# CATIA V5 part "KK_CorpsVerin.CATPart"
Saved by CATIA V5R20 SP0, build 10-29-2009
Part number: Corps de verin accouplement
Bounding box of the stored display mesh (mm): x -175.976 to 175.976, y -111.998 to 798.499, z -2473.558 to -1168.002
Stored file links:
  G:\Khaled_CFAO_2011\ST2M\ST2M_GR2\aboulegue\Khaled\CAD_thinkMOTION\KK_CorpsVerin.CATPart
  G:\Khaled_CFAO_2011\ST2M\ST2M_GR2\aboulegue\Khaled\CAD_thinkMOTION\KK_Train_Atterrissage.CATProduct
  G:\Khaled_CFAO_2011\ST2M\ST2M_GR2\aboulegue\Khaled\CAD_thinkMOTION\KK_SqueletteVerin.CATPart
  G:\Khaled_CFAO_2011\ST2M\ST2M_GR2\aboulegue\Khaled\CAD_thinkMOTION\KK_SquelettePanneau_Pivotant.CATPart
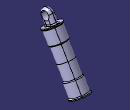
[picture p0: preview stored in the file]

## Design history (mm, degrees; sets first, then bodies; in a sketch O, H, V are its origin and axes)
External parameters (linked from other documents)
  `External.Longueur corps de verin` = 1280 mm
Set1
  Plane1 "Plan reference": linked copy from another document
  Line1: linked copy from another document
  Point1: linked copy from another document
  Line2: linked copy from another document
  Line3: linked copy from another document
  Point2 "Point.13": linked copy from another document
Body1 (main body)
  Sketch1 on Plane1, origin (0, 0, 0), H (0, 1, 0), V (0, 0, 1)
    point P1 (80.8287, -1418.0823)
    line L1 (80.8287, -1418.0823) -> (363.729, -1901.3704)
    line L2 (363.729, -1901.3704) -> (488.0031, -1828.6246)
    line L3 (488.0031, -1828.6246) -> (342.5115, -1580.0764)
    line L4 (342.5115, -1580.0764) -> (356.3197, -1571.9936)
    line L5 (356.3197, -1571.9936) -> (226.9939, -1351.0619)
    line L6 (226.9939, -1351.0619) -> (240.8021, -1342.979)
    line L7 (240.8021, -1342.979) -> (232.7192, -1329.1708)
    line L8 (232.7192, -1329.1708) -> (80.8287, -1418.0823)
    reference projected line E1 (0, -1280) -> (711.2923, -2495.1244) from Line1
    reference projected point E2 (0, -1280) from Point1
    length L1 = 560 {= (`External.Longueur corps de verin` -160mm)/2}
    length L2 = 144
    length L8 = 176
    length L6 = 16
    length L5 = 256
    length L3 = 288
    distance P1 E2 = 160
    perpendicularity: L2 L1
    parallelism: L3 L1, L4 L2, L5 L3, L6 L4, L7 L5, L8 L2
    coincidence: L1 E1
  Shaft1: profile Sketch1, axis Line1, angle 360
  Mirror1: of Shaft1, about face of Shaft1 from Sketch1.L2
  Sketch2 on Plane1, origin (0, 0, 0), H (0, 1, 0), V (0, 0, 1)
    line L1 (-15.8289, -1474.6624) -> (-96.6576, -1336.5801)
    arc A1 centre (0, -1280) radius 112 from (-96.6576, -1336.5801) to (96.6576, -1223.4199) cw
    point P3 (0, -1280)
    line L2 (96.6576, -1223.4199) -> (177.4863, -1361.5022)
    line L3 (177.4863, -1361.5022) -> (-15.8289, -1474.6624)
    reference projected line E1 (0, -1280) -> (711.2923, -2495.1244) from Line1
    reference projected point E2 (0, -1280) from Point1
    reference projected line E3 (0, -1280) -> (711.2923, -2495.1244) from Line1
    length L1 = 160
    length L3 = 224
    radius A1 = 112
    tangency: A1 L1, L2 A1
    perpendicularity: L3 L1
    parallelism: L1 E1, L1 E3
    coincidence: P3 E2
  Sketch3 on face of Shaft1 from Sketch1.L8, origin (0, 632.3307, -1095.2519), H (1, 0, 0), V (0, 0.863, 0.5052)
    line L1 (-64, -527.0415) -> (64, -527.0415)
    line L2 (64, -527.0415) -> (64, -751.0415)
    line L3 (64, -751.0415) -> (-64, -751.0415)
    line L4 (-64, -751.0415) -> (-64, -527.0415)
    reference projected line E1 (0, -640) -> (0, 754.5228) from Line2
    reference projected line E2 (-200, -639.0415) -> (200, -639.0415) from Line3
    length L3 = 128
    length L4 = 224
    distance L4 E1 = 64
    distance L1 E2 = 112
    horizontal: L1 H, L3 H
    vertical: L2 V, L4 V
  SolidCombine1: FirstComponentProfile Sketch2, FirstComponentDirection Sketch2, SecondComponentProfile Sketch3, SecondComponentDirection Sketch3
  Sketch4 on face of SolidCombine1 from Sketch3.L2, origin (64, 0, 0), H (0, 1, 0), V (0, 0, 1)
    circle A1 centre (0, -1280) radius 80
    point P1 (0, -1280)
    reference projected point E1 (0, -1280) from Point1
    radius A1 = 80
    coincidence: P1 E1
  Pocket1: profile Sketch4, direction (-1, 0, 0), through (limit type 3)
  Fillet1: radius 63, on edge [face of SolidCombine1 from Sketch2.A1 | face of SolidCombine1 from Sketch3.L2]
  Fillet2: radius 63, on edge [face of SolidCombine1 from Sketch2.A1 | face of SolidCombine1 from Sketch3.L4]
  Fillet3: radius 20, on edge [face of Shaft1 from Sketch1.L8 | face of SolidCombine1 from Sketch3.L2]; edge [face of Shaft1 from Sketch1.L8 | face of Fillet1] (x2); edge [face of SolidCombine1 from Sketch3.L4 | face of Shaft1 from Sketch1.L8]; edge [face of Shaft1 from Sketch1.L8 | face of Fillet2]
  Sketch5 on face of Mirror1, origin (0, 1191.679, -2065.6051), H (-1, 0, 0), V (0, 0.863, 0.5052)
    circle A1 centre (0, -631.5649) radius 80
    point P1 (0, -631.5649)
    reference projected point E1 (0, -631.5649) from Point2
    radius A1 = 80
    coincidence: P1 E1
  Pocket2: profile Sketch5, direction (0, -0.5052, 0.863), length 1080 {= `External.Longueur corps de verin`-200mm}
  Fillet4: radius 16, on edge [face of Shaft1 from Sketch1.L6 | face of Shaft1 from Sketch1.L5]; edge [face of Shaft1 from Sketch1.L4 | face of Mirror1]
  Fillet5: radius 16, on edge [face of Mirror1 | face of Mirror1] (x2)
